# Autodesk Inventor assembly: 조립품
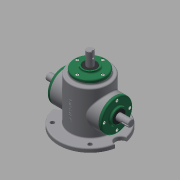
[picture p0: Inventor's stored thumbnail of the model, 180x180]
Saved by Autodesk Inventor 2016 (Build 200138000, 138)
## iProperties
Created: 2018-04
Part Number: 조립품
Material: 일반
Document SubType Name: Assembly
Designer: 605-15
Author: 605-15
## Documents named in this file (16)
- C:\Users\605-15\Desktop\480407V1006\조립품.iam
- C:\Users\605-15\Desktop\480407V1006\본체.ipt
- C:\Users\605-15\Desktop\480407V1006\커버.ipt
- C:\Users\605-15\Desktop\480407V1006\오일 실.ipt
- 오일 실.ipt
- C:\Users\605-15\Desktop\480407V1006\베어링 6203.ipt
- C:\Users\605-15\Desktop\480407V1006\메인 축.ipt
- 메인 축.ipt
- C:\Users\605-15\Desktop\480407V1006\서브 축.ipt
- 서브 축.ipt
- C:\Users\605-15\Desktop\480407V1006\키 5x5.ipt
- C:\Users\605-15\Desktop\480407V1006\키 4x4.ipt
- C:\Users\605-15\Desktop\480407V1006\메인 베벨기어.ipt
- C:\Users\605-15\Desktop\480407V1006\서브 베벨기어.ipt
- C:\Users\605-15\Desktop\480407V1006\볼트 M4.ipt
- 볼트 M4.ipt
